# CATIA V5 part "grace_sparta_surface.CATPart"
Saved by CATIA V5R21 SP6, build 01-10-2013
Part number: grace_sparta_surface
Bounding box of the stored display mesh (mm): x -1599.25 to 1577.25, y -973.806 to 973.806, z -984 to 486.317
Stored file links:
  C:\Users\gmarch\Dropbox\Thermosphere_Density_Data\Geometry_mod\GRACE\modifications\final_model\grace_sparta_surface.CATPart
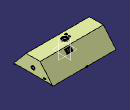
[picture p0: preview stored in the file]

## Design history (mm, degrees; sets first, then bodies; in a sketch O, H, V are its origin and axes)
Set1
  DatumSurface1
Body1 (main body)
